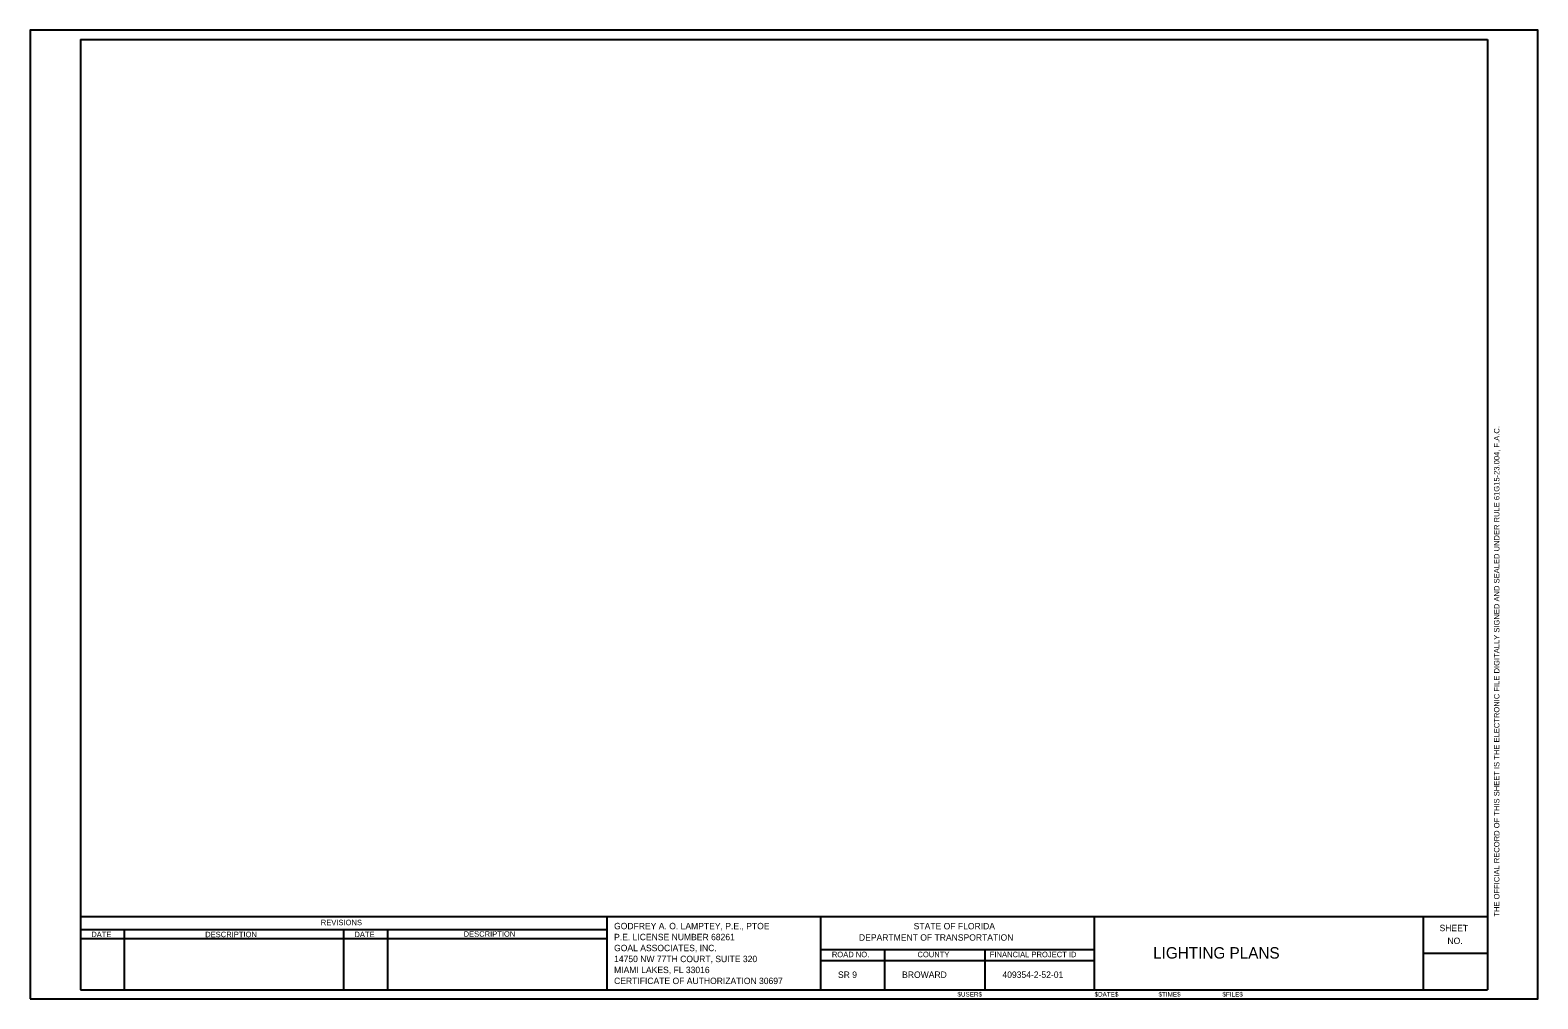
# Model space of a CAD drawing. Extents: x -816.7 to -800.2, y -2197.9 to -2187.3.
import ezdxf

# ---------------------------------------------------------------- set-up
doc = ezdxf.new("R2010")
doc.units = 0
for name, color, linetype in [('AdhocPoint_dp', 7, 'Continuous'), ('PlotBorder_dp', 7, 'Continuous'), ('SheetBorder_dp', 7, 'Continuous'), ('SheetLines_dp', 7, 'Continuous'), ('TextMinor', 7, 'Continuous'), ('TextMisc', 7, 'Continuous'), ('TextNotes', 7, 'Continuous')]:
    doc.layers.add(name, color=color, linetype=linetype)

msp = doc.modelspace()

# ---------------------------------------------------------------- linework, layer by layer
at = {"layer": 'AdhocPoint_dp'}
msp.add_line((-816.669, -2197.899), (-816.669, -2197.899), dxfattribs=at)
msp.add_line((-816.669, -2197.899), (-816.669, -2197.899), dxfattribs=at)
at = {"layer": 'PlotBorder_dp'}
msp.add_lwpolyline([(-816.669, -2197.899), (-800.169, -2197.899), (-800.169, -2187.299), (-816.669, -2187.299)], close=True, dxfattribs=at)
at = {"layer": 'SheetBorder_dp'}
for p, q in [((-816.119, -2187.399), (-816.119, -2197.799)), ((-816.119, -2187.399), (-800.719, -2187.399)), ((-800.719, -2187.399), (-800.719, -2197.799)), ((-816.119, -2196.999), (-800.719, -2196.999)), ((-816.119, -2197.799), (-800.719, -2197.799))]:
    msp.add_line(p, q, dxfattribs=at)
at = {"layer": 'SheetLines_dp'}
for p, q in [((-816.119, -2197.139), (-810.359, -2197.139)), ((-815.639, -2197.139), (-815.639, -2197.799)), ((-813.239, -2197.139), (-813.239, -2197.799)), ((-812.759, -2197.139), (-812.759, -2197.799)), ((-810.359, -2196.999), (-810.359, -2197.799)), ((-808.019, -2196.999), (-808.019, -2197.799)), ((-805.019, -2197.799), (-805.019, -2196.999)), ((-801.419, -2197.799), (-801.419, -2196.999)), ((-816.119, -2197.239), (-810.359, -2197.239)), ((-808.019, -2197.359), (-805.019, -2197.359)), ((-807.319, -2197.359), (-807.319, -2197.799)), ((-806.219, -2197.359), (-806.219, -2197.799)), ((-801.419, -2197.399), (-800.719, -2197.399)), ((-808.019, -2197.479), (-805.019, -2197.479))]:
    msp.add_line(p, q, dxfattribs=at)

# ---------------------------------------------------------------- texts
at = {"layer": 'TextMinor'}
msp.add_text('$USER$', height=0.05, dxfattribs=at).set_placement((-806.52, -2197.874))
for s, p in [('$DATE$', (-805.02, -2197.874)), ('$TIME$', (-804.32, -2197.874)), ('$FILE$', (-803.62, -2197.874))]:
    msp.add_text(s, height=0.05, rotation=360, dxfattribs=at).set_placement(p)
at = {"layer": 'TextMisc'}
for s, height, rotation, p in [('THE OFFICIAL RECORD OF THIS SHEET IS THE ELECTRONIC FILE DIGITALLY SIGNED AND SEALED UNDER RULE 61G15-23.004, F.A.C.', 0.06, 90, (-800.589, -2196.999)), ('SHEET', 0.07, 359.8607, (-801.244, -2197.158)), ('DATE', 0.06, 359.8693, (-816, -2197.223)), ('DESCRIPTION', 0.06, 0.0498, (-814.753, -2197.224)), ('DATE', 0.06, 359.8693, (-813.12, -2197.223)), ('DESCRIPTION', 0.06, 0.0498, (-811.925, -2197.219)), ('NO.', 0.07, 359.8607, (-801.158, -2197.298))]:
    msp.add_text(s, height=height, rotation=rotation, dxfattribs=at).set_placement(p)
for s, height, p in [('REVISIONS', 0.06, (-813.488, -2197.093)), ('STATE OF FLORIDA', 0.07, (-806.999, -2197.138)), ('DEPARTMENT OF TRANSPORTATION', 0.07, (-807.598, -2197.262)), ('ROAD NO.', 0.06, (-807.895, -2197.443)), ('COUNTY', 0.06, (-806.958, -2197.443)), ('FINANCIAL PROJECT ID', 0.06, (-806.166, -2197.443)), ('        LIGHTING PLANS         ', 0.125, (-804.75, -2197.458)), (' SR 9  ', 0.07, (-807.854, -2197.669)), ('  BROWARD   ', 0.07, (-807.178, -2197.669)), ('409354-2-52-01', 0.07, (-806.028, -2197.669))]:
    msp.add_text(s, height=height, dxfattribs=at).set_placement(p)
at = {"layer": 'TextNotes'}
for s, p in [('GODFREY A. O. LAMPTEY, P.E., PTOE', (-810.278, -2197.137)), ('P.E. LICENSE NUMBER 68261', (-810.278, -2197.257)), ('GOAL ASSOCIATES, INC.', (-810.278, -2197.377)), ('14750 NW 77TH COURT, SUITE 320', (-810.278, -2197.497)), ('MIAMI LAKES, FL 33016', (-810.278, -2197.617)), ('CERTIFICATE OF AUTHORIZATION 30697', (-810.278, -2197.737))]:
    msp.add_text(s, height=0.07, dxfattribs=at).set_placement(p)

doc.saveas('drawing.dxf')
